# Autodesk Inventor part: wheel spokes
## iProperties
Author: Administrator
Created: 2001-03
Part Number: wheel spokes
Document SubType Name: Modeling
Designer: Administrator
Control State: 0
Master: False
Checked Out: False
PropertySet Name: Design Tracking Control
Shininess: 0.0
PropertySet Name: _Private Model Information
Density: 0.0
Volumn: 0.0
Area: 0.0
PropertySet Name: Model Information
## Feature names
1. Revolution1
2. Shell1
3. Revolution2
4. Extrusion1
5. Fillet1
6. Fillet2
7. Circular Pattern1
8. Extrusion2
9. Mirror1
10. Hole1
